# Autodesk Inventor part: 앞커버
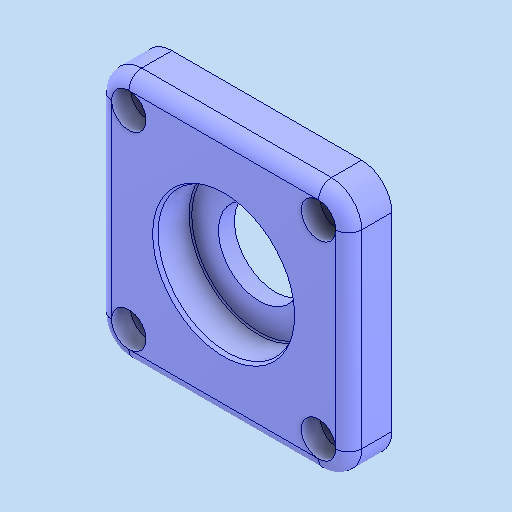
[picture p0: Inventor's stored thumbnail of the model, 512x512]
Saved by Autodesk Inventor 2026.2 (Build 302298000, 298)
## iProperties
Created: 2026-01
Part Number: 앞커버
Material: 알루미늄 6061
Document SubType Name: Modeling
Designer: PC2-07
Density: 2.7 g/cm^3
Appearance: 기본값
Author: jhkim
Sending System: Autodesk Inventor 2026
Preprocessor: ST-DEVELOPER v20.1
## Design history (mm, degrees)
feature "솔리드1"
node "솔리드2"
